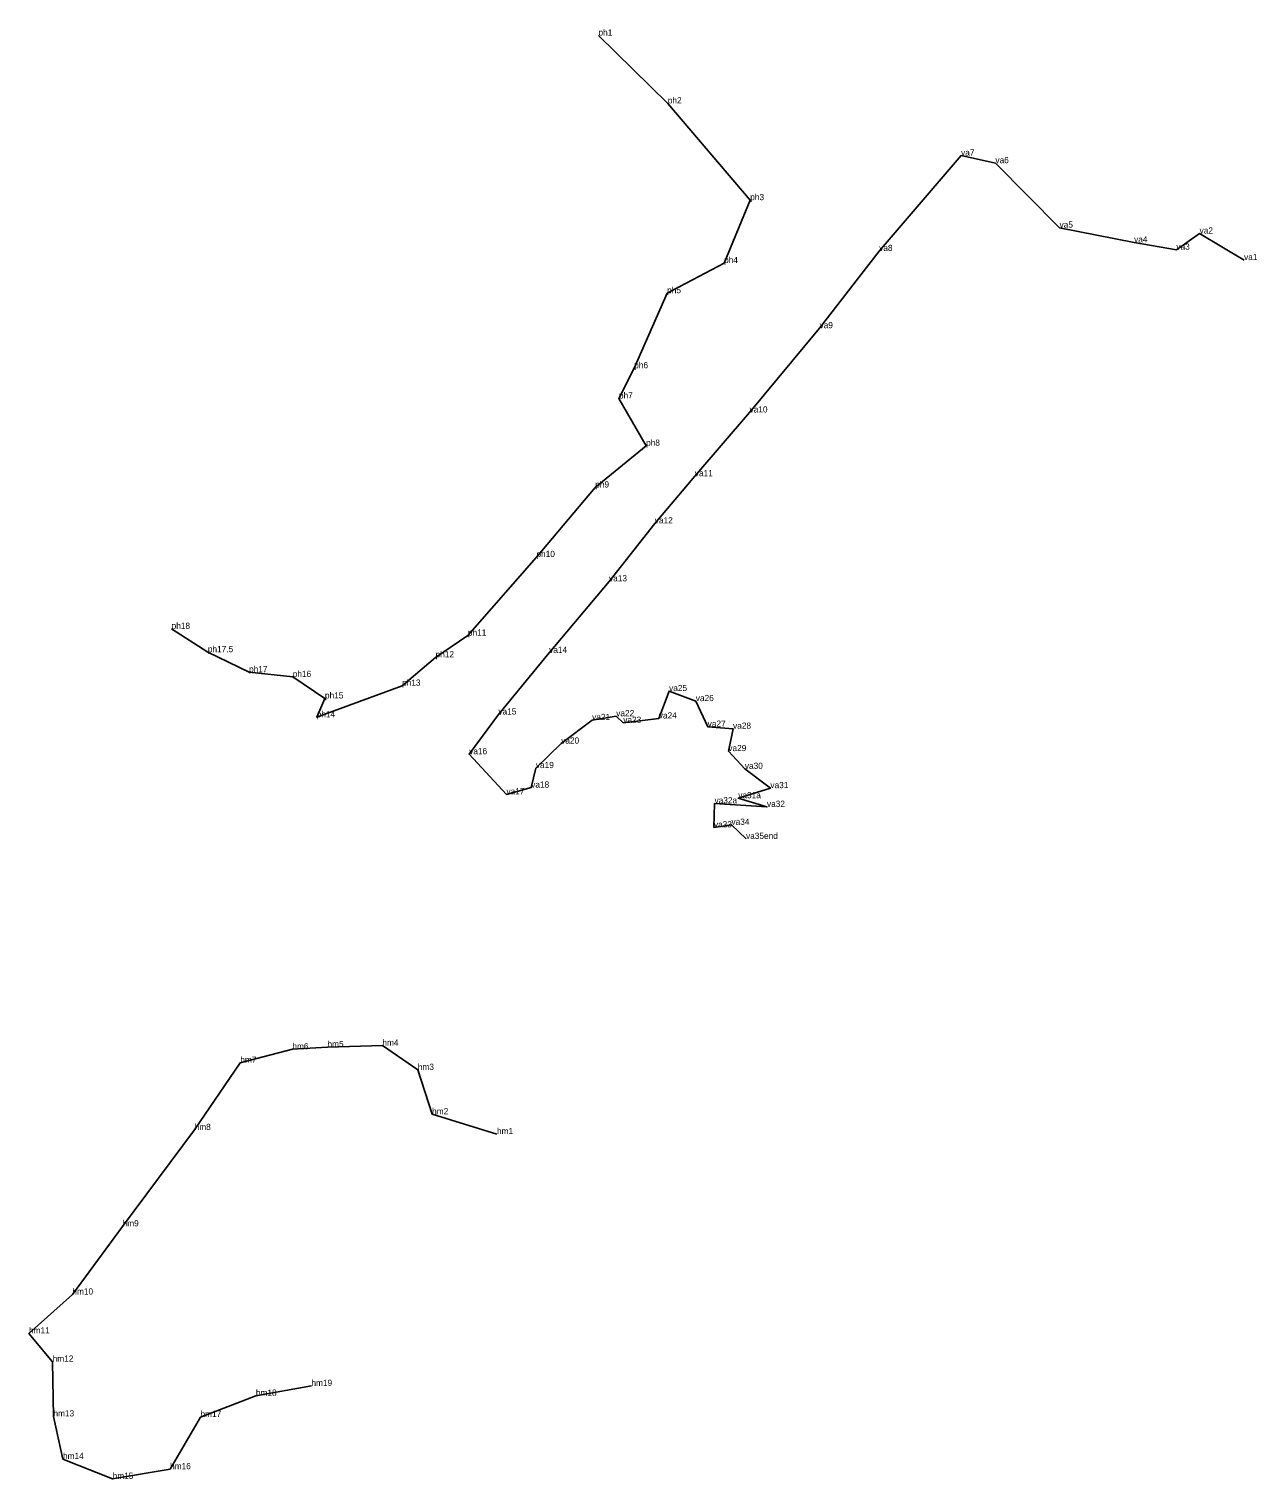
# Model space of a CAD drawing. Extents: x 2072529 to 2267990, y 436423 to 470008.
# Drawn here: x 2173124 to 2174115, y 447172 to 448342 of the extents above; entities that cross this region are included whole.
import ezdxf

# ---------------------------------------------------------------- set-up
doc = ezdxf.new("R2010")
doc.units = 0
doc.layers.add('Level 3', color=7, linetype='Continuous')
doc.layers.add('Old_Level_52', color=7, linetype='Continuous')

msp = doc.modelspace()

# ---------------------------------------------------------------- linework, layer by layer
at = {"layer": 'Level 3'}
for p, q in [((2173583.466, 448337), (2173583.466, 448337)), ((2173639.399, 448282.22), (2173639.399, 448282.22)), ((2173876.017, 448240.104), (2173876.017, 448240.104)), ((2173903.753, 448233.99), (2173903.753, 448233.99)), ((2173705.912, 448204.16), (2173705.912, 448204.16)), ((2173955.521, 448181.963), (2173955.521, 448181.963)), ((2174015.642, 448170.074), (2174015.642, 448170.074)), ((2174068.516, 448177.248), (2174068.516, 448177.248)), ((2173809.946, 448163.115), (2173809.946, 448163.115)), ((2174049.767, 448164.155), (2174049.767, 448164.155)), ((2174104.347, 448155.801), (2174104.347, 448155.801)), ((2173684.778, 448153.416), (2173684.778, 448153.416)), ((2173638.87, 448129.059), (2173638.87, 448129.059)), ((2173761.851, 448100.844), (2173761.851, 448100.844)), ((2173612.299, 448068.551), (2173612.299, 448068.551)), ((2173599.96, 448044.129), (2173599.96, 448044.129)), ((2173705.376, 448032.846), (2173705.376, 448032.846)), ((2173621.865, 448005.978), (2173621.865, 448005.978)), ((2173661.232, 447981.429), (2173661.232, 447981.429)), ((2173580.838, 447972.298), (2173580.838, 447972.298)), ((2173628.918, 447943.374), (2173628.918, 447943.374)), ((2173533.431, 447916.219), (2173533.431, 447916.219)), ((2173591.986, 447896.56), (2173591.986, 447896.56)), ((2173239.026, 447858.262), (2173239.026, 447858.262)), ((2173478.1, 447852.84), (2173478.1, 447852.84)), ((2173268.278, 447839.435), (2173268.278, 447839.435)), ((2173543.675, 447838.894), (2173543.675, 447838.894)), ((2173452.001, 447835.245), (2173452.001, 447835.245)), ((2173301.538, 447823.257), (2173301.538, 447823.257)), ((2173336.772, 447819.459), (2173336.772, 447819.459)), ((2173425.014, 447812.384), (2173425.014, 447812.384)), ((2173640.445, 447808.038), (2173640.445, 447808.038)), ((2173362.745, 447802.115), (2173362.745, 447802.115)), ((2173661.975, 447799.96), (2173661.975, 447799.96)), ((2173356.081, 447786.898), (2173356.081, 447786.898)), ((2173502.708, 447789.134), (2173502.708, 447789.134)), ((2173578.339, 447784.692), (2173578.339, 447784.692)), ((2173597.789, 447787.733), (2173597.789, 447787.733)), ((2173603.446, 447782.457), (2173603.446, 447782.457)), ((2173632.137, 447785.936), (2173632.137, 447785.936)), ((2173671.593, 447779.273), (2173671.593, 447779.273)), ((2173692.052, 447777.639), (2173692.052, 447777.639)), ((2173479.117, 447757.064), (2173479.117, 447757.064)), ((2173553.392, 447765.678), (2173553.392, 447765.678)), ((2173688.234, 447759.607), (2173688.234, 447759.607)), ((2173532.95, 447745.903), (2173532.95, 447745.903)), ((2173701.582, 447745.298), (2173701.582, 447745.298)), ((2173509.211, 447724.724), (2173509.211, 447724.724)), ((2173529.203, 447730.149), (2173529.203, 447730.149)), ((2173696.239, 447721.595), (2173696.239, 447721.595)), ((2173722.187, 447729.723), (2173722.187, 447729.723)), ((2173677.109, 447717.448), (2173677.109, 447717.448)), ((2173719.425, 447714.583), (2173719.425, 447714.583)), ((2173690.789, 447700.137), (2173690.789, 447700.137)), ((2173676.612, 447698.048), (2173676.612, 447698.048)), ((2173702.522, 447688.766), (2173702.522, 447688.766)), ((2173336.468, 447518.995), (2173336.468, 447518.995)), ((2173364.809, 447520.816), (2173364.809, 447520.816)), ((2173409.121, 447521.961), (2173409.121, 447521.961)), ((2173294.448, 447508.114), (2173294.448, 447508.114)), ((2173437.702, 447502.381), (2173437.702, 447502.381)), ((2173449.257, 447466.546), (2173449.257, 447466.546)), ((2173257.628, 447453.931), (2173257.628, 447453.931)), ((2173501.562, 447450.544), (2173501.562, 447450.544)), ((2173199.479, 447376.158), (2173199.479, 447376.158)), ((2173158.954, 447321.157), (2173158.954, 447321.157)), ((2173123.958, 447289.75), (2173123.958, 447289.75)), ((2173143.038, 447266.952), (2173143.038, 447266.952)), ((2173351.848, 447247.454), (2173351.848, 447247.454)), ((2173307.042, 447239.465), (2173307.042, 447239.465)), ((2173143.681, 447222.783), (2173143.681, 447222.783)), ((2173262.347, 447222.318), (2173262.347, 447222.318)), ((2173151.353, 447188.418), (2173151.353, 447188.418)), ((2173191.46, 447172.374), (2173191.46, 447172.374)), ((2173237.811, 447180.175), (2173237.811, 447180.175))]:
    msp.add_line(p, q, dxfattribs=at)
at = {"layer": 'Old_Level_52'}
for points in [[(2173583.466, 448337), (2173639.399, 448282.22), (2173705.912, 448204.16), (2173684.778, 448153.416), (2173638.87, 448129.059), (2173612.299, 448068.551), (2173599.96, 448044.129), (2173621.865, 448005.978), (2173580.838, 447972.298), (2173533.431, 447916.219), (2173478.1, 447852.84), (2173452.001, 447835.245), (2173425.014, 447812.384), (2173356.081, 447786.898), (2173362.745, 447802.115), (2173336.772, 447819.459), (2173301.538, 447823.257), (2173268.278, 447839.435), (2173239.026, 447858.262)], [(2173702.522, 447688.766), (2173690.789, 447700.137), (2173676.612, 447698.048), (2173677.109, 447717.448), (2173719.425, 447714.583), (2173696.239, 447721.595), (2173722.187, 447729.723), (2173701.582, 447745.298), (2173688.234, 447759.607), (2173692.052, 447777.639), (2173671.593, 447779.273), (2173661.975, 447799.96), (2173640.445, 447808.038), (2173632.137, 447785.936), (2173603.446, 447782.457), (2173597.789, 447787.733), (2173578.339, 447784.692), (2173553.392, 447765.678), (2173532.95, 447745.903), (2173529.203, 447730.149), (2173509.211, 447724.724), (2173479.117, 447757.064), (2173502.708, 447789.134), (2173543.675, 447838.894), (2173591.986, 447896.56), (2173628.918, 447943.374), (2173661.232, 447981.429), (2173705.376, 448032.846), (2173761.851, 448100.844), (2173809.946, 448163.115), (2173876.017, 448240.104), (2173903.753, 448233.99), (2173955.521, 448181.963), (2174015.642, 448170.074), (2174049.767, 448164.155), (2174068.516, 448177.248), (2174104.347, 448155.801)], [(2173501.562, 447450.544), (2173449.257, 447466.546), (2173437.702, 447502.381), (2173409.121, 447521.961), (2173364.809, 447520.816), (2173336.468, 447518.995), (2173294.448, 447508.114), (2173257.628, 447453.931), (2173199.479, 447376.158), (2173158.954, 447321.157), (2173123.958, 447289.75), (2173143.038, 447266.952), (2173143.681, 447222.783), (2173151.353, 447188.418), (2173191.46, 447172.374), (2173237.811, 447180.175), (2173262.347, 447222.318), (2173307.042, 447239.465), (2173351.848, 447247.454)]]:
    msp.add_lwpolyline(points, dxfattribs=at)

# ---------------------------------------------------------------- texts
for s, p in [('ph1', (2173583.466, 448337)), ('ph2', (2173639.399, 448282.22)), ('va7', (2173876.017, 448240.104)), ('va6', (2173903.753, 448233.99)), ('ph3', (2173705.912, 448204.16)), ('va5', (2173955.521, 448181.963)), ('va2', (2174068.516, 448177.248)), ('va8', (2173809.946, 448163.115)), ('va4', (2174015.642, 448170.074)), ('va3', (2174049.767, 448164.155)), ('ph4', (2173684.778, 448153.416)), ('va1', (2174104.347, 448155.801)), ('ph5', (2173638.87, 448129.059)), ('va9', (2173761.851, 448100.844)), ('ph6', (2173612.299, 448068.551)), ('ph7', (2173599.96, 448044.129)), ('va10', (2173705.376, 448032.846)), ('ph8', (2173621.865, 448005.978)), ('va11', (2173661.232, 447981.429)), ('ph9', (2173580.838, 447972.298)), ('va12', (2173628.918, 447943.374)), ('ph10', (2173533.431, 447916.219)), ('va13', (2173591.986, 447896.56)), ('ph18', (2173239.026, 447858.262)), ('ph11', (2173478.1, 447852.84)), ('ph17.5', (2173268.278, 447839.435)), ('ph12', (2173452.001, 447835.245)), ('va14', (2173543.675, 447838.894)), ('ph17', (2173301.538, 447823.257)), ('ph16', (2173336.772, 447819.459)), ('ph13', (2173425.014, 447812.384)), ('ph15', (2173362.745, 447802.115)), ('va25', (2173640.445, 447808.038)), ('va26', (2173661.975, 447799.96)), ('ph14', (2173356.081, 447786.898)), ('va15', (2173502.708, 447789.134)), ('va22', (2173597.789, 447787.733)), ('va21', (2173578.339, 447784.692)), ('va23', (2173603.446, 447782.457)), ('va24', (2173632.137, 447785.936)), ('va27', (2173671.593, 447779.273)), ('va28', (2173692.052, 447777.639)), ('va20', (2173553.392, 447765.678)), ('va16', (2173479.117, 447757.064)), ('va29', (2173688.234, 447759.607)), ('va19', (2173532.95, 447745.903)), ('va30', (2173701.582, 447745.298)), ('va18', (2173529.203, 447730.149)), ('va31', (2173722.187, 447729.723)), ('va17', (2173509.211, 447724.724)), ('va32a', (2173677.109, 447717.448)), ('va31a', (2173696.239, 447721.595)), ('va32', (2173719.425, 447714.583)), ('va33', (2173676.612, 447698.048)), ('va34', (2173690.789, 447700.137)), ('va35end', (2173702.522, 447688.766)), ('hm6', (2173336.468, 447518.995)), ('hm5', (2173364.809, 447520.816)), ('hm4', (2173409.121, 447521.961)), ('hm7', (2173294.448, 447508.114)), ('hm3', (2173437.702, 447502.381)), ('hm2', (2173449.257, 447466.546)), ('hm8', (2173257.628, 447453.931)), ('hm1', (2173501.562, 447450.544)), ('hm9', (2173199.479, 447376.158)), ('hm10', (2173158.954, 447321.157)), ('hm11', (2173123.958, 447289.75)), ('hm12', (2173143.038, 447266.952)), ('hm18', (2173307.042, 447239.465)), ('hm19', (2173351.848, 447247.454)), ('hm13', (2173143.681, 447222.783)), ('hm17', (2173262.347, 447222.318)), ('hm14', (2173151.353, 447188.418)), ('hm16', (2173237.811, 447180.175)), ('hm15', (2173191.46, 447172.374))]:
    msp.add_text(s, height=5).set_placement(p)

doc.saveas('drawing.dxf')
